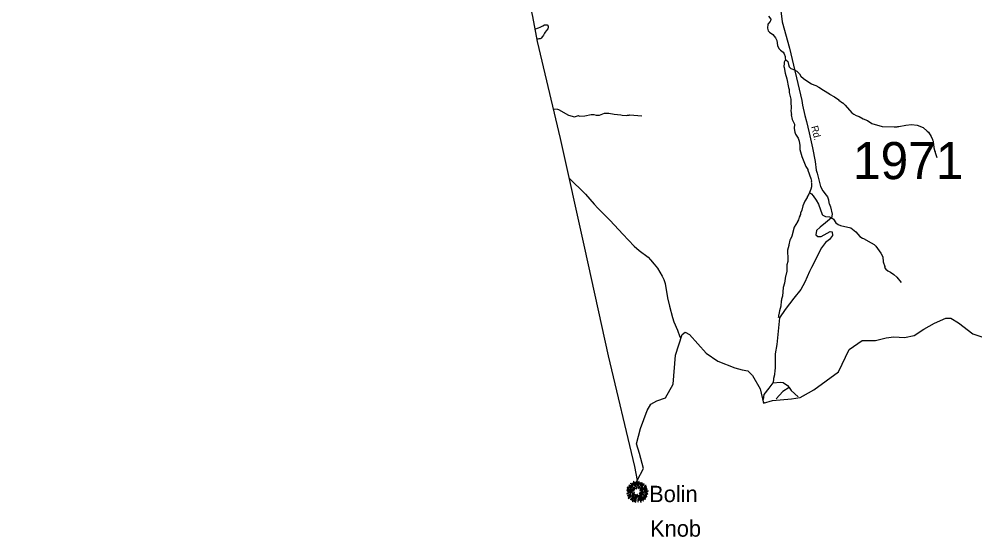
# Model space of a CAD drawing. Extents: x 1113032 to 1302912, y 664689 to 832535.
# Drawn here: x 1152008 to 1164889, y 675378 to 682356 of the extents above; entities that cross this region are included whole.
import ezdxf

# ---------------------------------------------------------------- set-up
doc = ezdxf.new("R2010")
doc.units = 0
for name, color, linetype in [('Exist Boundary Political CountyLine', 7, 'Continuous'), ('Exist Geographical Mountain Summit CELL', 7, 'Continuous'), ('Exist Geographical Mountain Summit Label', 7, 'Continuous'), ('Exist Hydrographic Misc Water Feature', 7, 'Continuous'), ('Exist Road Non-System Type 51', 7, 'Continuous'), ('Exist Road Secondary Type 51 Attributed', 7, 'Continuous'), ('Exist Road Secondary Type 51 Label', 7, 'Continuous'), ('Exist Road Secondary Type 51 Number Label', 7, 'Continuous')]:
    doc.layers.add(name, color=color, linetype=linetype)

msp = doc.modelspace()

# ---------------------------------------------------------------- linework, layer by layer
at = {"layer": 'Exist Boundary Political CountyLine'}
for points in [[(1148405, 729150), (1156119, 694505), (1156386, 693319), (1156931, 691026), (1157284, 689489), (1157953, 686676), (1158628, 683719), (1158926, 682391), (1158991, 682054), (1159298, 680748), (1159630, 679270), (1159949, 677818), (1160303, 676325), (1160338, 676140)], [(1160338, 676140), (1160425, 676299), (1160370, 676504), (1160329, 676634), (1160383, 676840), (1160473, 677080), (1160521, 677169), (1160603, 677210), (1160719, 677251), (1160822, 677436), (1160856, 677826), (1160946, 678107), (1160987, 678135), (1161042, 678107), (1161268, 677854), (1161425, 677744), (1161652, 677655), (1161755, 677628), (1161830, 677614), (1161892, 677552), (1161994, 677374), (1162042, 677182), (1162162, 677217), (1162416, 677237), (1162533, 677258), (1162718, 677360), (1163052, 677601), (1163197, 677902), (1163372, 678023), (1163551, 678025), (1163695, 678059), (1163797, 678073), (1163941, 678066), (1164072, 678094), (1164202, 678176), (1164346, 678258), (1164497, 678326), (1164565, 678326), (1164668, 678265), (1164864, 678114), (1165049, 678052)]]:
    msp.add_lwpolyline(points, dxfattribs=at)
at = {"layer": 'Exist Geographical Mountain Summit CELL'}
for points in [[(1160324, 676130), (1160328, 676078), (1160331, 676078), (1160330, 676131)], [(1160198, 676002), (1160270, 675995), (1160271, 675998), (1160198, 676007)], [(1160201, 676023), (1160242, 676014), (1160244, 676017), (1160202, 676028)], [(1160204, 676043), (1160226, 676034), (1160228, 676037), (1160205, 676048)], [(1160226, 676054), (1160252, 676037), (1160254, 676040), (1160229, 676058)], [(1160227, 676072), (1160266, 676042), (1160269, 676044), (1160230, 676077)], [(1160242, 676026), (1160273, 676014), (1160274, 676016), (1160245, 676030)], [(1160247, 676097), (1160283, 676060), (1160286, 676062), (1160251, 676102)], [(1160255, 676070), (1160288, 676041), (1160290, 676043), (1160258, 676075)], [(1160275, 676099), (1160290, 676077), (1160292, 676078), (1160279, 676103)], [(1160279, 676031), (1160304, 676012), (1160306, 676015), (1160281, 676034)], [(1160279, 676001), (1160296, 675999), (1160297, 676001), (1160280, 676006)], [(1160286, 676120), (1160312, 676054), (1160315, 676055), (1160291, 676123)], [(1160298, 676044), (1160312, 676028), (1160314, 676030), (1160302, 676047)], [(1160319, 676069), (1160322, 676069), (1160313, 676117), (1160309, 676116)], [(1160330, 676057), (1160331, 676027), (1160334, 676028), (1160334, 676057)], [(1160340, 676076), (1160344, 676076), (1160348, 676123), (1160342, 676123)], [(1160352, 676047), (1160367, 676124), (1160362, 676126), (1160349, 676048)], [(1160355, 676026), (1160358, 676024), (1160407, 676108), (1160402, 676112)], [(1160370, 676083), (1160373, 676082), (1160383, 676108), (1160378, 676110)], [(1160373, 676007), (1160375, 676005), (1160424, 676041), (1160421, 676045)], [(1160377, 676027), (1160379, 676025), (1160434, 676089), (1160430, 676094)], [(1160390, 676004), (1160391, 676002), (1160470, 676031), (1160468, 676035)], [(1160414, 676099), (1160393, 676065), (1160396, 676064), (1160418, 676095)], [(1160434, 676032), (1160462, 676047), (1160459, 676052), (1160433, 676035)], [(1160434, 676055), (1160436, 676053), (1160459, 676069), (1160455, 676072)], [(1160436, 676004), (1160473, 676011), (1160471, 676016), (1160435, 676006)], [(1160197, 675965), (1160198, 675959), (1160234, 675970), (1160232, 675973)], [(1160207, 675937), (1160209, 675932), (1160255, 675952), (1160253, 675957)], [(1160211, 675985), (1160240, 675986), (1160240, 675990), (1160209, 675990)], [(1160218, 675900), (1160221, 675896), (1160249, 675917), (1160247, 675921)], [(1160224, 675921), (1160253, 675938), (1160251, 675941), (1160222, 675926)], [(1160243, 675976), (1160244, 675971), (1160277, 675979), (1160276, 675983)], [(1160249, 675881), (1160252, 675878), (1160293, 675926), (1160290, 675928)], [(1160264, 675912), (1160284, 675930), (1160280, 675932), (1160260, 675915)], [(1160261, 675930), (1160264, 675927), (1160298, 675955), (1160296, 675958)], [(1160289, 675912), (1160264, 675873), (1160267, 675870), (1160293, 675910)], [(1160270, 675962), (1160273, 675957), (1160301, 675972), (1160300, 675975)], [(1160274, 675853), (1160279, 675850), (1160290, 675875), (1160286, 675877)], [(1160292, 675890), (1160297, 675889), (1160323, 675947), (1160321, 675948)], [(1160299, 675940), (1160302, 675937), (1160313, 675953), (1160311, 675955)], [(1160304, 675855), (1160316, 675898), (1160312, 675898), (1160299, 675856)], [(1160314, 675845), (1160318, 675844), (1160331, 675933), (1160328, 675934)], [(1160339, 675949), (1160343, 675912), (1160347, 675912), (1160342, 675950)], [(1160345, 675890), (1160349, 675848), (1160353, 675849), (1160350, 675890)], [(1160355, 675940), (1160364, 675910), (1160368, 675912), (1160357, 675941)], [(1160365, 675874), (1160359, 675904), (1160356, 675904), (1160361, 675873)], [(1160364, 675961), (1160402, 675925), (1160405, 675930), (1160365, 675963)], [(1160370, 675938), (1160420, 675863), (1160424, 675866), (1160372, 675939)], [(1160370, 675895), (1160387, 675845), (1160391, 675847), (1160373, 675896)], [(1160375, 675978), (1160435, 675966), (1160437, 675970), (1160376, 675981)], [(1160380, 675901), (1160396, 675872), (1160400, 675874), (1160384, 675902)], [(1160389, 675991), (1160389, 675989), (1160419, 675989), (1160420, 675994)], [(1160389, 675958), (1160467, 675920), (1160468, 675925), (1160390, 675961)], [(1160402, 675912), (1160432, 675883), (1160435, 675886), (1160404, 675915)], [(1160419, 675913), (1160449, 675887), (1160452, 675891), (1160421, 675916)], [(1160428, 675924), (1160453, 675911), (1160455, 675914), (1160430, 675928)], [(1160433, 675990), (1160485, 675994), (1160485, 675998), (1160433, 675994)], [(1160442, 675948), (1160463, 675940), (1160465, 675944), (1160443, 675951)], [(1160447, 675978), (1160474, 675976), (1160474, 675981), (1160448, 675982)], [(1160451, 675961), (1160480, 675954), (1160480, 675959), (1160452, 675966)]]:
    msp.add_lwpolyline(points, close=True, dxfattribs=at)
at = {"layer": 'Exist Hydrographic Misc Water Feature'}
for p, q in [((1160911, 678072), (1160930, 678057)), ((1162576, 677281), (1162719, 677358)), ((1162038, 677198), (1162052, 677185))]:
    msp.add_line(p, q, dxfattribs=at)
for points in [[(1162110, 682396), (1162138, 682355), (1162137, 682331), (1162132, 682323), (1162097, 682290), (1162093, 682236), (1162105, 682196), (1162120, 682179), (1162165, 682147)], [(1158959, 682221), (1159007, 682237), (1159032, 682248), (1159065, 682264), (1159089, 682277), (1159099, 682280), (1159115, 682279), (1159125, 682278), (1159132, 682274), (1159136, 682267), (1159139, 682260), (1159139, 682251), (1159138, 682239), (1159132, 682227), (1159110, 682199), (1159097, 682181), (1159087, 682168), (1159074, 682140), (1159061, 682120), (1159046, 682099), (1159039, 682094), (1159031, 682091), (1159012, 682089), (1158997, 682084), (1158986, 682078)], [(1162165, 682147), (1162201, 682104), (1162218, 682067), (1162231, 682002), (1162249, 681962), (1162270, 681937), (1162307, 681909), (1162320, 681890), (1162333, 681854), (1162334, 681830), (1162339, 681811)], [(1162339, 681811), (1162321, 681774), (1162317, 681759), (1162315, 681719), (1162320, 681702), (1162331, 681626), (1162356, 681553), (1162377, 681436), (1162386, 681407), (1162388, 681367), (1162408, 681278), (1162407, 681254), (1162411, 681246), (1162409, 681206), (1162413, 681198), (1162412, 681166), (1162415, 681158), (1162411, 681118), (1162417, 681072), (1162415, 681066), (1162429, 681005), (1162458, 680940), (1162455, 680880), (1162465, 680832), (1162474, 680807), (1162506, 680750), (1162520, 680709), (1162530, 680653), (1162531, 680597), (1162555, 680504), (1162610, 680369), (1162640, 680328), (1162636, 680322), (1162679, 680206), (1162686, 680174), (1162685, 680158), (1162689, 680150), (1162686, 680094), (1162677, 680062), (1162661, 680021)], [(1162339, 681811), (1162367, 681784), (1162376, 681746), (1162388, 681714), (1162411, 681689), (1162459, 681671), (1162489, 681654), (1162526, 681617), (1162544, 681586), (1162579, 681555), (1162624, 681522), (1162686, 681484), (1162717, 681469), (1162748, 681460), (1162788, 681440), (1162850, 681397), (1162930, 681349), (1162932, 681344), (1162998, 681309), (1163054, 681268), (1163056, 681262), (1163103, 681228), (1163111, 681226), (1163142, 681197), (1163232, 681095), (1163257, 681073), (1163288, 681056), (1163328, 681044), (1163382, 681012), (1163444, 680990), (1163500, 680951), (1163642, 680909), (1163802, 680902), (1163818, 680905), (1163842, 680904), (1163850, 680908), (1163866, 680907), (1163959, 680927), (1164036, 680936), (1164112, 680928), (1164194, 680893), (1164248, 680848), (1164264, 680832), (1164301, 680776), (1164320, 680735), (1164319, 680727), (1164327, 680711), (1164326, 680695), (1164333, 680671), (1164335, 680623), (1164346, 680590), (1164345, 680582), (1164353, 680566), (1164352, 680558), (1164363, 680533), (1164375, 680493)], [(1159205, 681145), (1159262, 681142), (1159278, 681138), (1159411, 681060), (1159494, 681040), (1159549, 681058), (1159551, 681054), (1159565, 681049), (1159631, 681051), (1159720, 681071), (1159752, 681069), (1159784, 681060), (1159832, 681062), (1159897, 681087), (1159955, 681088), (1160027, 681076), (1160120, 681065), (1160136, 681061), (1160200, 681058), (1160208, 681061), (1160232, 681060), (1160240, 681064), (1160400, 681053)], [(1159418, 680216), (1159642, 679998), (1159757, 679862), (1159808, 679808), (1159976, 679642), (1160144, 679456), (1160298, 679295), (1160363, 679237), (1160485, 679146), (1160518, 679113), (1160569, 679054), (1160610, 678998), (1160677, 678893), (1160698, 678847), (1160717, 678791), (1160748, 678600), (1160775, 678486), (1160816, 678333), (1160833, 678278), (1160880, 678165), (1160911, 678072)], [(1162661, 680021), (1162650, 679999), (1162628, 679960), (1162628, 679952), (1162598, 679901), (1162571, 679839), (1162557, 679783), (1162539, 679740), (1162538, 679724), (1162530, 679708), (1162529, 679700), (1162521, 679685), (1162511, 679653), (1162498, 679630), (1162498, 679622), (1162455, 679551), (1162422, 679433), (1162401, 679381), (1162395, 679378), (1162383, 679313), (1162384, 679306), (1162364, 679243), (1162363, 679187), (1162370, 679171), (1162367, 679091), (1162357, 679043), (1162353, 678948), (1162349, 678940), (1162343, 678900), (1162339, 678892), (1162322, 678797), (1162304, 678738), (1162295, 678622), (1162285, 678584), (1162285, 678566), (1162280, 678559), (1162273, 678487), (1162254, 678424), (1162248, 678376), (1162244, 678368), (1162243, 678344), (1162238, 678330)], [(1162661, 680021), (1162686, 680000), (1162711, 679973), (1162751, 679915), (1162780, 679862), (1162833, 679723), (1162842, 679715), (1162874, 679697), (1162929, 679691), (1162961, 679680), (1162984, 679659), (1163016, 679611), (1163045, 679590), (1163077, 679573), (1163219, 679542), (1163283, 679490), (1163341, 679425), (1163374, 679404), (1163390, 679399), (1163491, 679342), (1163530, 679317), (1163553, 679296), (1163621, 679201), (1163647, 679152), (1163655, 679086), (1163674, 679022), (1163673, 679010), (1163688, 678986), (1163717, 678965), (1163751, 678947), (1163798, 678915), (1163836, 678877), (1163895, 678807)]]:
    msp.add_lwpolyline(points, dxfattribs=at)
at = {"layer": 'Exist Road Non-System Type 51'}
for points in [[(1162920, 679881), (1162925, 679869), (1162942, 679828), (1162965, 679726), (1162957, 679676), (1162878, 679610), (1162803, 679551), (1162757, 679505), (1162744, 679448), (1162775, 679425), (1162819, 679425), (1162937, 679492), (1162965, 679489), (1162971, 679438), (1162930, 679388), (1162876, 679344), (1162822, 679273), (1162689, 679009), (1162662, 678953), (1162599, 678813), (1162544, 678711), (1162449, 678596), (1162331, 678444), (1162254, 678329), (1162218, 677973), (1162198, 677844), (1162198, 677646), (1162193, 677623), (1162190, 677564), (1162175, 677513), (1162169, 677456)], [(1162039, 677228), (1162049, 677295), (1162116, 677382), (1162169, 677456)], [(1162169, 677456), (1162267, 677465), (1162307, 677458), (1162362, 677418), (1162386, 677390)], [(1162386, 677390), (1162301, 677337), (1162211, 677238)], [(1162386, 677390), (1162414, 677351), (1162506, 677264)]]:
    msp.add_lwpolyline(points, dxfattribs=at)
at = {"layer": 'Exist Road Secondary Type 51 Attributed'}
msp.add_lwpolyline([(1162236, 682758), (1162293, 682317), (1162389, 681964), (1162555, 681260), (1162568, 681198), (1162599, 681059), (1162619, 680976), (1162654, 680822), (1162702, 680622), (1162737, 680435), (1162750, 680322), (1162762, 680278), (1162807, 680099), (1162839, 680041), (1162884, 679984), (1162905, 679959), (1162918, 679921), (1162920, 679881)], dxfattribs=at)

# ---------------------------------------------------------------- texts
at = {"layer": 'Exist Geographical Mountain Summit Label'}
for s, p in [('Bolin', (1160499, 675847)), ('Knob', (1160512, 675381))]:
    msp.add_text(s, height=220, dxfattribs=at).set_placement(p)
at = {"layer": 'Exist Road Secondary Type 51 Label'}
msp.add_text('Rd.', height=95, rotation=284.4267, dxfattribs=at).set_placement((1162680, 680907))
at = {"layer": 'Exist Road Secondary Type 51 Number Label'}
msp.add_text('1971', height=500, dxfattribs=at).set_placement((1163247, 680199))

doc.saveas('drawing.dxf')
